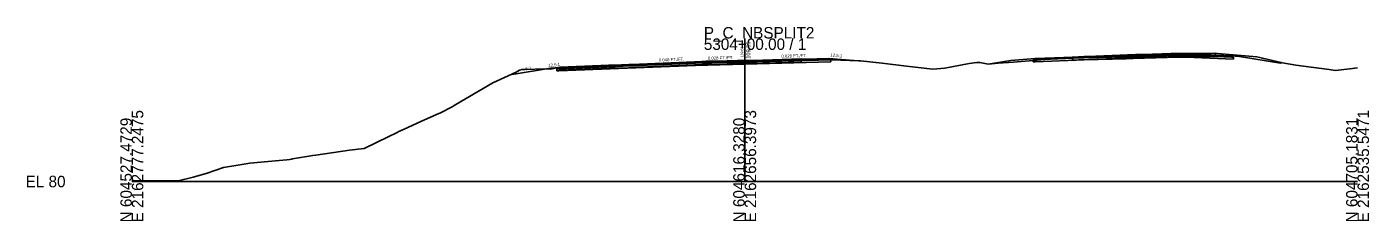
# Model space of a CAD drawing. Extents: x -26 to 1303, y -10 to 12038.
# Drawn here: x 974.3 to 1302.8, y -9.7 to 37.8 of the extents above; entities that cross this region are included whole.
import ezdxf

# ---------------------------------------------------------------- set-up
doc = ezdxf.new("R2010")
doc.units = 0
for name, color, linetype in [('RD_GPK_XS_Cell', 7, 'Continuous'), ('RD_XS_Base', 7, 'Continuous'), ('RD_XS_ExGround', 7, 'Continuous'), ('RD_XS_ExPaveRet', 7, 'Continuous'), ('RD_XS_Greenside', 7, 'Continuous'), ('RD_XS_Pave', 7, 'Continuous'), ('RD_XS_PaveOvlay_CP', 7, 'Continuous'), ('RD_XS_TieSlope', 7, 'Continuous'), ('RD_XS_TX_Elev_EX', 7, 'Continuous'), ('RD_XS_TX_Elev_PR', 7, 'Continuous'), ('RD_XS_TX_ShdSlope', 7, 'Continuous'), ('RD_XS_TX_Slope', 7, 'Continuous')]:
    doc.layers.add(name, color=color, linetype=linetype)

msp = doc.modelspace()

# ---------------------------------------------------------------- linework, layer by layer
at = {"layer": 'RD_GPK_XS_Cell'}
for p, q in [((1150, 0), (1150, 35)), ((1000, 0), (1150, 0)), ((1150, 0), (1300, 0))]:
    msp.add_line(p, q, dxfattribs=at)
at = {"layer": 'RD_XS_Base'}
for p, q in [((1150, 29.23), (1171.08, 29.78)), ((1170.58, 29.77), (1170.58, 29.77)), ((1171.08, 29.78), (1171.08, 29.28)), ((1171.08, 29.75), (1171.08, 29.75)), ((1221.08, 29.77), (1220.61, 29.75)), ((1220.61, 29.75), (1220.61, 29.72)), ((1220.61, 29.72), (1220.61, 29.25)), ((1221.11, 29.77), (1221.08, 29.77)), ((1230.46, 30.15), (1221.11, 29.77)), ((1221.11, 29.27), (1233.11, 29.75)), ((1233.11, 30.25), (1230.46, 30.15)), ((1230.46, 29.65), (1231.11, 29.67)), ((1243.36, 30.54), (1233.11, 30.25)), ((1233.11, 29.75), (1243.36, 30.04)), ((1245.11, 30.59), (1243.36, 30.54)), ((1243.36, 30.04), (1245.11, 30.09)), ((1256.18, 30.9), (1245.11, 30.59)), ((1245.11, 30.74), (1245.11, 30.75)), ((1245.11, 30.75), (1245.11, 30.7)), ((1245.11, 30.59), (1245.11, 30.74)), ((1245.11, 30.7), (1245.11, 30.09)), ((1245.11, 30.59), (1245.11, 30.59)), ((1245.11, 30.59), (1245.11, 30.59)), ((1245.11, 30.55), (1245.11, 30.59)), ((1245.11, 30.09), (1245.11, 30.55)), ((1245.11, 30.09), (1256.18, 30.4)), ((1257.11, 30.93), (1256.18, 30.9)), ((1256.18, 30.4), (1257.11, 30.43)), ((1258.04, 30.89), (1257.11, 30.93)), ((1257.11, 30.43), (1258.08, 30.39)), ((1269.11, 30.45), (1258.04, 30.89)), ((1258.08, 30.39), (1269.61, 29.93)), ((1269.15, 30.44), (1269.11, 30.45)), ((1269.61, 30.43), (1269.15, 30.44)), ((1269.61, 30.38), (1269.61, 30.43)), ((1269.61, 29.93), (1269.61, 30.38)), ((1104.51, 27.58), (1104.01, 27.56)), ((1104.01, 27.56), (1104.01, 27.56)), ((1104.01, 27.56), (1104.01, 27.06)), ((1104.01, 27.06), (1104.51, 27.08)), ((1138, 28.92), (1104.51, 27.58)), ((1104.51, 27.08), (1138, 28.42)), ((1104.51, 27.58), (1104.51, 27.58)), ((1104.51, 27.08), (1104.51, 27.08)), ((1150, 29.23), (1138, 28.92)), ((1138, 28.92), (1138, 28.92)), ((1138, 28.42), (1150, 28.73)), ((1138, 28.42), (1138, 28.42)), ((1150, 28.73), (1150, 29.39)), ((1150, 29.39), (1150, 29.39)), ((1150, 29.39), (1150, 29.39)), ((1150, 29.39), (1150, 29.23)), ((1171.08, 29.28), (1150, 28.73)), ((1150, 29.23), (1150, 29.23)), ((1150, 28.73), (1150, 29.23)), ((1150, 29.23), (1150, 29.23)), ((1150, 29.23), (1150, 29.23)), ((1150, 28.73), (1150, 28.73)), ((1220.61, 29.25), (1221.08, 29.27)), ((1221.08, 29.27), (1221.11, 29.27))]:
    msp.add_line(p, q, dxfattribs=at)
at = {"layer": 'RD_XS_ExGround'}
msp.add_lwpolyline([(1000, 0.16), (1008.57, 0.2), (1009.13, 0.19), (1011.37, 0.15), (1015.01, 1.05), (1018.19, 2), (1020.58, 2.74), (1022.44, 3.45), (1025.94, 3.99), (1028.88, 4.46), (1036.03, 5.13), (1037.96, 5.28), (1038.65, 5.37), (1039.11, 5.5), (1039.36, 5.54), (1044.3, 6.4), (1045.04, 6.48), (1053.25, 7.65), (1056.89, 8.09), (1062.75, 10.92), (1064.77, 11.93), (1065.34, 12.21), (1066.62, 12.78), (1070.76, 14.69), (1074.55, 16.36), (1075.59, 16.79), (1078.38, 18.24), (1078.69, 18.46), (1079.31, 18.87), (1088.38, 24.15), (1094.08, 26.77), (1094.87, 27.22), (1095.53, 27.41), (1096.16, 27.39), (1101.17, 27.6), (1102.54, 27.53), (1104.76, 28.02), (1116.71, 28.47), (1117.37, 28.5), (1117.94, 28.5), (1121.68, 28.6), (1122.31, 28.64), (1124.27, 28.73), (1139.57, 29.4), (1140.59, 29.42), (1145.71, 29.5), (1146.02, 29.5), (1146.26, 29.51), (1148.32, 29.63), (1151.01, 29.63), (1151.69, 29.65), (1154.48, 29.7), (1163.86, 29.99), (1171.41, 29.8), (1177.83, 29.55), (1178.33, 29.51), (1183.65, 28.92), (1189.58, 28.25), (1196.08, 27.49), (1199, 27.77), (1204.94, 28.87), (1206.84, 29.14), (1207.59, 29.11), (1209.62, 28.73), (1212.06, 28.94), (1215.78, 29.2), (1219.6, 29.5), (1228.08, 30.26), (1230.22, 30.45), (1232.08, 30.52), (1245.69, 31.04), (1245.91, 31.04), (1247.65, 31.09), (1254.33, 31.3), (1263.02, 31.35), (1265.23, 31.37), (1265.76, 31.32), (1275.35, 30.5), (1281.64, 29.06), (1284.91, 28.45), (1293.08, 27.38), (1294.53, 27.15), (1298.08, 27.6), (1300, 27.83)], dxfattribs=at)
at = {"layer": 'RD_XS_ExPaveRet'}
for points in [[(1163.86, 29.99), (1163.86, 29.99), (1163.86, 29.24), (1163.86, 29.24), (1163.86, 29.24), (1154.48, 28.95), (1154.48, 28.95), (1151.69, 28.9), (1151.01, 28.88), (1151.01, 28.88), (1148.32, 28.88), (1148.32, 28.88), (1148.32, 28.88), (1146.26, 28.76), (1146.02, 28.75), (1146.02, 28.75), (1145.71, 28.75), (1145.71, 28.75), (1140.59, 28.67), (1140.59, 28.67), (1140.59, 28.67), (1139.57, 28.65), (1139.57, 28.65), (1124.27, 27.98), (1124.27, 27.98), (1122.31, 27.89), (1121.68, 27.85), (1121.68, 27.85), (1121.68, 27.85), (1117.94, 27.75), (1117.94, 27.75), (1117.37, 27.75), (1116.71, 27.72), (1116.71, 27.72), (1104.76, 27.27), (1104.76, 27.27), (1104.76, 28.02), (1104.76, 28.02), (1104.76, 28.02), (1116.71, 28.47), (1116.71, 28.47), (1117.37, 28.5), (1117.94, 28.5), (1117.94, 28.5), (1121.68, 28.6), (1121.68, 28.6), (1121.68, 28.6), (1122.31, 28.64), (1124.27, 28.73), (1124.27, 28.73), (1139.57, 29.4), (1139.57, 29.4), (1140.59, 29.42), (1140.59, 29.42), (1140.59, 29.42), (1145.71, 29.5), (1145.71, 29.5), (1146.02, 29.5), (1146.02, 29.5), (1146.26, 29.51), (1148.32, 29.63), (1148.32, 29.63), (1148.32, 29.63), (1151.01, 29.63), (1151.01, 29.63), (1151.69, 29.65), (1154.48, 29.7), (1154.48, 29.7), (1163.86, 29.99), (1163.86, 29.99), (1163.86, 29.99)], [(1154.48, 29.7), (1151.69, 29.65), (1151.01, 29.63), (1148.32, 29.63), (1146.26, 29.51), (1146.02, 29.5), (1145.71, 29.5), (1140.59, 29.42), (1139.57, 29.4), (1124.27, 28.73), (1122.31, 28.64), (1121.68, 28.6), (1117.94, 28.5), (1117.37, 28.5), (1116.71, 28.47), (1104.76, 28.02), (1104.76, 27.27), (1116.71, 27.72), (1117.37, 27.75), (1117.94, 27.75), (1121.68, 27.85), (1122.31, 27.89), (1124.27, 27.98), (1139.57, 28.65), (1140.59, 28.67), (1145.71, 28.75), (1146.02, 28.75), (1146.26, 28.76), (1148.32, 28.88), (1151.01, 28.88), (1151.69, 28.9), (1154.48, 28.95), (1163.86, 29.24), (1163.86, 29.99), (1154.48, 29.7)], [(1265.23, 31.37), (1265.23, 31.29), (1265.23, 30.62), (1265.22, 30.62), (1264.1, 30.61), (1254.44, 30.55), (1254.27, 30.54), (1253.66, 30.53), (1246.42, 30.31), (1246.27, 30.3), (1245.76, 30.29), (1245.69, 30.29), (1244.77, 30.25), (1232.08, 29.77), (1231.68, 29.75), (1230.22, 29.7), (1230.22, 30.4), (1230.22, 30.45), (1231.68, 30.5), (1232.08, 30.52), (1244.77, 31), (1245.69, 31.04), (1245.76, 31.04), (1246.27, 31.05), (1246.42, 31.06), (1253.66, 31.28), (1254.27, 31.29), (1254.44, 31.3), (1264.1, 31.36), (1265.22, 31.37), (1265.23, 31.37)], [(1265.22, 31.37), (1264.1, 31.36), (1254.44, 31.3), (1254.27, 31.29), (1253.66, 31.28), (1246.42, 31.06), (1246.27, 31.05), (1245.76, 31.04), (1245.69, 31.04), (1244.77, 31), (1232.08, 30.52), (1231.68, 30.5), (1230.22, 30.45), (1230.22, 30.4), (1230.22, 29.7), (1231.68, 29.75), (1232.08, 29.77), (1244.77, 30.25), (1245.69, 30.29), (1245.76, 30.29), (1246.27, 30.3), (1246.42, 30.31), (1253.66, 30.53), (1254.27, 30.54), (1254.44, 30.55), (1264.1, 30.61), (1265.22, 30.62), (1265.23, 30.62), (1265.23, 31.29), (1265.23, 31.37), (1265.22, 31.37)]]:
    msp.add_lwpolyline(points, dxfattribs=at)
at = {"layer": 'RD_XS_Greenside'}
for p, q in [((1215.11, 29.61), (1210.05, 28.77)), ((1271.11, 30.6), (1281.11, 28.94)), ((1102.51, 27.74), (1092.58, 26.08)), ((1281.11, 28.94), (1281.48, 29.12))]:
    msp.add_line(p, q, dxfattribs=at)
at = {"layer": 'RD_XS_Pave'}
for p, q in [((1170.58, 30.08), (1150, 29.55)), ((1170.58, 29.92), (1150, 29.39)), ((1150, 29.39), (1170.58, 29.92)), ((1150, 29.23), (1170.58, 29.77)), ((1170.58, 29.92), (1170.58, 30.08)), ((1170.58, 30.08), (1170.58, 30.08)), ((1170.58, 29.77), (1170.58, 29.92)), ((1170.58, 29.92), (1170.58, 29.92)), ((1230.46, 30.46), (1221.11, 30.09)), ((1230.46, 30.31), (1221.11, 29.93)), ((1221.11, 29.93), (1230.46, 30.31)), ((1221.11, 29.77), (1230.46, 30.15)), ((1221.11, 30.09), (1221.11, 30.08)), ((1221.11, 30.08), (1221.11, 29.93)), ((1221.11, 29.93), (1221.11, 29.92)), ((1221.11, 29.92), (1221.11, 29.77)), ((1233.11, 30.57), (1230.46, 30.46)), ((1233.11, 30.41), (1230.46, 30.31)), ((1230.46, 30.31), (1233.11, 30.41)), ((1230.46, 30.15), (1233.11, 30.25)), ((1243.36, 30.86), (1233.11, 30.57)), ((1243.36, 30.7), (1233.11, 30.41)), ((1233.11, 30.41), (1243.36, 30.7)), ((1233.11, 30.25), (1243.36, 30.54)), ((1245.11, 30.91), (1243.36, 30.86)), ((1245.11, 30.75), (1243.36, 30.7)), ((1243.36, 30.7), (1245.11, 30.75)), ((1243.36, 30.54), (1245.11, 30.59)), ((1256.18, 31.22), (1245.11, 30.91)), ((1256.18, 31.06), (1245.11, 30.75)), ((1245.11, 30.75), (1256.18, 31.06)), ((1245.11, 30.59), (1256.18, 30.9)), ((1245.11, 30.74), (1245.11, 30.75)), ((1245.11, 30.75), (1245.11, 30.75)), ((1245.11, 30.75), (1245.11, 30.75)), ((1245.11, 30.75), (1245.11, 30.74)), ((1245.11, 30.59), (1245.11, 30.74)), ((1245.11, 30.74), (1245.11, 30.59)), ((1245.11, 30.59), (1245.11, 30.59)), ((1245.11, 30.59), (1245.11, 30.59)), ((1257.11, 31.24), (1256.18, 31.22)), ((1257.11, 31.08), (1256.18, 31.06)), ((1256.18, 31.06), (1257.11, 31.08)), ((1256.18, 30.9), (1257.11, 30.93)), ((1258.04, 31.21), (1257.11, 31.24)), ((1258.04, 31.05), (1257.11, 31.08)), ((1257.11, 31.08), (1258.04, 31.05)), ((1257.11, 30.93), (1258.04, 30.89)), ((1269.11, 30.76), (1258.04, 31.21)), ((1269.11, 30.6), (1258.04, 31.05)), ((1258.04, 31.05), (1269.11, 30.6)), ((1258.04, 30.89), (1269.11, 30.45)), ((1269.11, 30.75), (1269.11, 30.76)), ((1269.11, 30.6), (1269.11, 30.75)), ((1269.11, 30.59), (1269.11, 30.6)), ((1269.11, 30.45), (1269.11, 30.59)), ((1138, 29.24), (1104.51, 27.9)), ((1104.51, 27.74), (1138, 29.08)), ((1138, 29.08), (1104.51, 27.74)), ((1104.51, 27.58), (1138, 28.92)), ((1104.51, 27.9), (1104.51, 27.9)), ((1104.51, 27.9), (1104.51, 27.74)), ((1104.51, 27.74), (1104.51, 27.74)), ((1104.51, 27.74), (1104.51, 27.58)), ((1150, 29.55), (1138, 29.24)), ((1138, 29.08), (1150, 29.39)), ((1150, 29.39), (1138, 29.08)), ((1138, 29.24), (1138, 29.24)), ((1138, 28.92), (1150, 29.23)), ((1138, 29.08), (1138, 29.08)), ((1138, 29.08), (1138, 29.08)), ((1138, 28.92), (1138, 28.92)), ((1150, 29.55), (1150, 29.55)), ((1150, 29.39), (1150, 29.39)), ((1150, 29.39), (1150, 29.39)), ((1150, 29.39), (1150, 29.23)), ((1150, 29.39), (1150, 29.39)), ((1150, 29.23), (1150, 29.39)), ((1150, 29.39), (1150, 29.39)), ((1150, 29.39), (1150, 29.39)), ((1150, 29.23), (1150, 29.23)), ((1150, 29.23), (1150, 29.23))]:
    msp.add_line(p, q, dxfattribs=at)
at = {"layer": 'RD_XS_PaveOvlay_CP'}
for p, q in [((1170.58, 30.08), (1150, 29.55)), ((1230.46, 30.46), (1221.11, 30.09)), ((1233.11, 30.57), (1230.46, 30.46)), ((1243.36, 30.86), (1233.11, 30.57)), ((1245.11, 30.91), (1243.36, 30.86)), ((1256.18, 31.22), (1245.11, 30.91)), ((1257.11, 31.24), (1256.18, 31.22)), ((1258.04, 31.21), (1257.11, 31.24)), ((1269.11, 30.76), (1258.04, 31.21)), ((1138, 29.24), (1104.51, 27.9)), ((1150, 29.55), (1138, 29.24)), ((1138, 29.24), (1138, 29.24)), ((1150, 29.55), (1150, 29.55))]:
    msp.add_line(p, q, dxfattribs=at)
at = {"layer": 'RD_XS_TieSlope'}
for p, q in [((1170.58, 30.08), (1176.68, 29.6)), ((1221.11, 30.09), (1215.11, 29.61)), ((1269.11, 30.76), (1271.11, 30.6)), ((1104.51, 27.9), (1102.51, 27.74))]:
    msp.add_line(p, q, dxfattribs=at)

# ---------------------------------------------------------------- texts
at = {"layer": 'RD_GPK_XS_Cell'}
for s, p in [('P_C_NBSPLIT2', (1140, 35)), ('5304+00.00 / 1', (1140, 32.2)), ('EL 80', (974, -1.4))]:
    msp.add_text(s, height=2.8, dxfattribs=at).set_placement(p)
for s, p in [('E 2162777.2475', (1002.8, -10)), ('E 2162656.3973', (1152.8, -10)), ('E 2162535.5471', (1302.8, -10)), ('N 604527.4729', (1000, -10)), ('N 604616.3280', (1150, -10)), ('N 604705.1831', (1300, -10))]:
    msp.add_text(s, height=2.8, rotation=90, dxfattribs=at).set_placement(p)
at = {"layer": 'RD_XS_TX_Elev_EX'}
msp.add_text('109.63', height=0.6, rotation=90, dxfattribs=at).set_placement((1149.64, 30.44))
at = {"layer": 'RD_XS_TX_Elev_PR'}
msp.add_text('109.55', height=1, rotation=90, dxfattribs=at).set_placement((1151.37, 30.05))
at = {"layer": 'RD_XS_TX_ShdSlope'}
for rotation, p in [(355.4261, (1170.96, 30.58)), (4.5739, (1101.96, 28.03))]:
    msp.add_text('12.5:1', height=0.75, rotation=rotation, dxfattribs=at).set_placement(p)
at = {"layer": 'RD_XS_TX_Slope'}
for s, rotation, p in [('0.040 FT./FT.', 2.2906, (1128.99, 29.34)), ('0.028 FT./FT.', 1.6039, (1141, 29.78)), ('0.028 FT./FT.', 1.6039, (1159, 30.28)), ('0.028 FT./FT.', 1.6039, (1159, 30.28)), ('6:1', 9.4642, (1096.41, 27.2))]:
    msp.add_text(s, height=0.75, rotation=rotation, dxfattribs=at).set_placement(p)

doc.saveas('drawing.dxf')
